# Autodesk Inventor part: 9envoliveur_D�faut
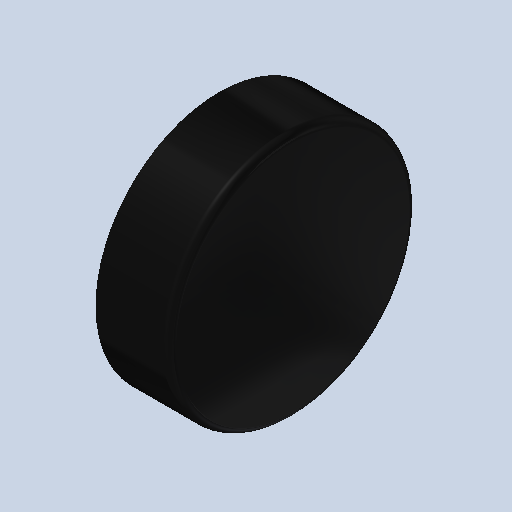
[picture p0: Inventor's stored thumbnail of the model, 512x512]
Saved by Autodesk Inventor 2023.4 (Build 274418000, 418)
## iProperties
Created: 2011-01
Part Number: 9envoliveur_D�faut
Document SubType Name: Modeling
Designer: eric
Density: 1 g/cm^3
Mass: 2.66 g
Surface Area: 35.6351 cm^2
Volume: 2.66 cm^3
Material: Générique
Appearance: Lustré - Noir
Author: eric
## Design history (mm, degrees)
feature "Base1"
node "Corps solides"
node "Corps surfaciques"
node "Solide1"
